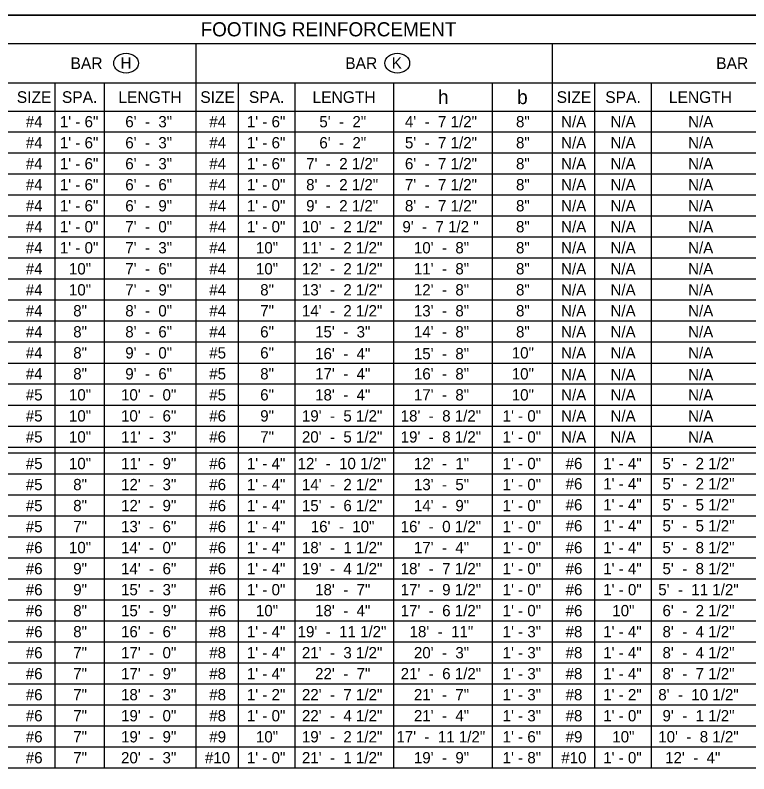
# Model space of a CAD drawing. Extents: x 99862 to 103151, y 100000 to 105076.
# Drawn here: x 100877 to 101917, y 104001 to 105076 of the extents above; entities that cross this region are included whole.
import ezdxf

# ---------------------------------------------------------------- set-up
doc = ezdxf.new("R2010")
doc.units = 0
for name, color, linetype in [('Level 1', 7, 'Continuous'), ('Level 20', 7, 'Continuous'), ('Level 4', 7, 'Continuous')]:
    doc.layers.add(name, color=color, linetype=linetype)

msp = doc.modelspace()

# ---------------------------------------------------------------- linework, layer by layer
at = {"layer": 'Level 1'}
msp.add_lwpolyline([(99862, 102999.5), (103151, 102999.5), (103151, 105075.5), (99862, 105075.5)], close=True, dxfattribs=at)
at = {"layer": 'Level 20'}
for centre in [(101034.5, 105007.5), (101418.9, 105007.5)]:
    msp.add_ellipse(centre, major_axis=(-17.5, 0), ratio=0.8, dxfattribs=at)
at = {"layer": 'Level 4'}
for p, q in [((100414, 105035.5), (102554, 105035.5)), ((101134, 104008.6), (101134, 105035.5)), ((101639, 104008.6), (101639, 105035.5)), ((100014, 104979.5), (102711, 104979.5)), ((100934, 104008.6), (100934, 104979.5)), ((101004, 104008.6), (101004, 104979.5)), ((101194, 104008.6), (101194, 104979.5)), ((101274, 104008.6), (101274, 104979.5)), ((101414, 104008.6), (101414, 104979.5)), ((101554, 104008.6), (101554, 104979.5)), ((101699, 104008.6), (101699, 104979.5)), ((101779, 104008.6), (101779, 104979.5)), ((99939, 104939.5), (103151, 104939.5)), ((103151, 104909.7), (99939, 104909.7)), ((103151, 104880), (99939, 104880)), ((103151, 104850.2), (99939, 104850.2)), ((103151, 104820.4), (99939, 104820.4)), ((103151, 104790.6), (99939, 104790.6)), ((103151, 104760.9), (99939, 104760.9)), ((103151, 104731.1), (99939, 104731.1)), ((103151, 104701.3), (99939, 104701.3)), ((103151, 104671.6), (99939, 104671.6)), ((103151, 104641.8), (99939, 104641.8)), ((103151, 104612), (99939, 104612)), ((103151, 104582.2), (99939, 104582.2)), ((103151, 104552.5), (99939, 104552.5)), ((103151, 104522.7), (99939, 104522.7)), ((103151, 104492.9), (99939, 104492.9)), ((103151, 104463.2), (99939, 104463.2)), ((103151, 104455.2), (99939, 104455.2)), ((103151, 104425.4), (99939, 104425.4)), ((103151, 104395.6), (99939, 104395.6)), ((103151, 104365.8), (99939, 104365.8)), ((103151, 104336.1), (99939, 104336.1)), ((103151, 104306.3), (99939, 104306.3)), ((103151, 104276.5), (99939, 104276.5)), ((103151, 104246.8), (99939, 104246.8)), ((103151, 104217), (99939, 104217)), ((103151, 104187.2), (99939, 104187.2)), ((103151, 104157.4), (99939, 104157.4)), ((103151, 104127.7), (99939, 104127.7)), ((103151, 104097.9), (99939, 104097.9)), ((103151, 104068.1), (99939, 104068.1)), ((103151, 104038.4), (99939, 104038.4))]:
    msp.add_line(p, q, dxfattribs=at)
for points in [[(99939, 105075.5), (103151, 105075.5)], [(103151, 104008.6), (99939, 104008.6), (99939, 105075.5)]]:
    msp.add_lwpolyline(points, dxfattribs=at)

# ---------------------------------------------------------------- texts
at = {"layer": 'Level 20'}
for s, height, p in [('FOOTING REINFORCEMENT', 20, (101140.2, 105045.5)), ('BAR', 16.5, (100955.8, 104999.2)), ('H', 16, (101026.7, 104999.7)), ('BAR', 16.5, (101345.1, 104999.2)), ('K', 16, (101411.1, 104999.7)), ('BAR', 16.5, (101870.8, 104999.2)), ('SIZE', 16.5, (100879.7, 104951.2)), ('SPA.', 16.5, (100943.6, 104951.2)), ('LENGTH', 16.5, (101023.7, 104951.2)), ('SIZE', 16.5, (101139.7, 104951.2)), ('SPA.', 16.5, (101208.6, 104951.2)), ('LENGTH', 16.5, (101298.7, 104951.2)), ('h', 20, (101476.6, 104949.5)), ('b', 20, (101588.8, 104949.5)), ('SIZE', 16.5, (101644.7, 104951.2)), ('SPA.', 16.5, (101713.6, 104951.2)), ('LENGTH', 16.5, (101803.7, 104951.2))]:
    msp.add_text(s, height=height, dxfattribs=at).set_placement(p)
for s, p in [('#4', (100892.4, 104916.6)), ('1\' - 6"', (100940.7, 104916.6)), ('6\'  -  3"', (101033.4, 104916.6)), ('#4', (101152.4, 104916.6)), ('1\' - 6"', (101205.7, 104916.6)), ('5\'  -  2"', (101308.4, 104916.6)), ('4\'  -  7 1/2"', (101429.7, 104916.6)), ('8"', (101587.1, 104916.6)), ('N/A', (101651, 104916.6)), ('N/A', (101721, 104916.6)), ('N/A', (101831, 104916.6)), ('5\'  -  7 1/2"', (101429.7, 104886.8)), ('N/A', (101651, 104886.8)), ('N/A', (101721, 104886.8)), ('N/A', (101831, 104886.8)), ('#4', (100892.4, 104886.8)), ('1\' - 6"', (100940.7, 104886.8)), ('6\'  -  3"', (101033.4, 104886.8)), ('#4', (101152.4, 104886.8)), ('1\' - 6"', (101205.7, 104886.8)), ('6\'  -  2"', (101308.4, 104886.8)), ('8"', (101587.1, 104886.8)), ('#4', (100892.4, 104857.1)), ('1\' - 6"', (100940.7, 104857.1)), ('6\'  -  3"', (101033.4, 104857.1)), ('#4', (101152.4, 104857.1)), ('1\' - 6"', (101205.7, 104857.1)), ('7\'  -  2 1/2"', (101289.7, 104857.1)), ('6\'  -  7 1/2"', (101429.7, 104857.1)), ('8"', (101587.1, 104857.1)), ('N/A', (101651, 104857.1)), ('N/A', (101721, 104857.1)), ('N/A', (101831, 104857.1)), ('#4', (100892.4, 104827.3)), ('1\' - 6"', (100940.7, 104827.3)), ('6\'  -  6"', (101033.4, 104827.3)), ('#4', (101152.4, 104827.3)), ('1\' - 0"', (101205.7, 104827.3)), ('8\'  -  2 1/2"', (101289.7, 104827.3)), ('7\'  -  7 1/2"', (101429.7, 104827.3)), ('8"', (101587.1, 104827.3)), ('N/A', (101651, 104827.3)), ('N/A', (101721, 104827.3)), ('N/A', (101831, 104827.3)), ('#4', (100892.4, 104797.5)), ('1\' - 6"', (100940.7, 104797.5)), ('6\'  -  9"', (101033.4, 104797.5)), ('#4', (101152.4, 104797.5)), ('1\' - 0"', (101205.7, 104797.5)), ('9\'  -  2 1/2"', (101289.7, 104797.5)), ('8\'  -  7 1/2"', (101429.7, 104797.5)), ('8"', (101587.1, 104797.5)), ('N/A', (101651, 104797.5)), ('N/A', (101721, 104797.5)), ('N/A', (101831, 104797.5)), ('#4', (100892.4, 104767.8)), ('1\' - 0"', (100940.7, 104767.8)), ('7\'  -  0"', (101033.4, 104767.8)), ('#4', (101152.4, 104767.8)), ('1\' - 0"', (101205.7, 104767.8)), ('10\'  -  2 1/2"', (101283.7, 104767.8)), ('9\'  -  7 1/2 "', (101426.1, 104767.8)), ('8"', (101587.1, 104767.8)), ('N/A', (101651, 104767.8)), ('N/A', (101721, 104767.8)), ('N/A', (101831, 104767.8)), ('#4', (100892.4, 104738)), ('1\' - 0"', (100940.7, 104738)), ('7\'  -  3"', (101033.4, 104738)), ('#4', (101152.4, 104738)), ('10"', (101218.6, 104738)), ('11\'  -  2 1/2"', (101283.7, 104738)), ('10\'  -  8"', (101442.4, 104738)), ('8"', (101587.1, 104738)), ('N/A', (101651, 104738)), ('N/A', (101721, 104738)), ('N/A', (101831, 104738)), ('#4', (100892.4, 104708.2)), ('10"', (100953.6, 104708.2)), ('7\'  -  6"', (101033.4, 104708.2)), ('#4', (101152.4, 104708.2)), ('10"', (101218.6, 104708.2)), ('12\'  -  2 1/2"', (101283.7, 104708.2)), ('11\'  -  8"', (101442.4, 104708.2)), ('8"', (101587.1, 104708.2)), ('N/A', (101651, 104708.2)), ('N/A', (101721, 104708.2)), ('N/A', (101831, 104708.2)), ('#4', (100892.4, 104678.4)), ('10"', (100953.6, 104678.4)), ('7\'  -  9"', (101033.4, 104678.4)), ('#4', (101152.4, 104678.4)), ('8"', (101224.6, 104678.4)), ('13\'  -  2 1/2"', (101283.7, 104678.4)), ('12\'  -  8"', (101442.4, 104678.4)), ('8"', (101587.1, 104678.4)), ('N/A', (101651, 104678.4)), ('N/A', (101721, 104678.4)), ('N/A', (101831, 104678.4)), ('#4', (100892.4, 104648.7)), ('8"', (100959.6, 104648.7)), ('8\'  -  0"', (101033.4, 104648.7)), ('#4', (101152.4, 104648.7)), ('7"', (101224.6, 104648.7)), ('14\'  -  2 1/2"', (101283.7, 104648.7)), ('13\'  -  8"', (101442.4, 104648.7)), ('8"', (101587.1, 104648.7)), ('N/A', (101651, 104648.7)), ('N/A', (101721, 104648.7)), ('N/A', (101831, 104648.7)), ('#4', (100892.4, 104618.9)), ('8"', (100959.6, 104618.9)), ('8\'  -  6"', (101033.4, 104618.9)), ('#4', (101152.4, 104618.9)), ('6"', (101224.6, 104618.9)), ('15\'  -  3"', (101302.4, 104618.9)), ('14\'  -  8"', (101442.4, 104618.9)), ('8"', (101587.1, 104618.9)), ('N/A', (101651, 104618.9)), ('N/A', (101721, 104618.9)), ('N/A', (101831, 104618.9)), ('#4', (100892.4, 104589.1)), ('8"', (100959.6, 104589.1)), ('9\'  -  0"', (101033.4, 104589.1)), ('#5', (101152.4, 104589.1)), ('6"', (101224.6, 104589.1)), ('16\'  -  4"', (101302.4, 104588)), ('15\'  -  8"', (101442.4, 104588)), ('10"', (101581.1, 104589.1)), ('N/A', (101651, 104589.1)), ('N/A', (101721, 104589.1)), ('N/A', (101831, 104589.1)), ('#4', (100892.4, 104559.4)), ('8"', (100959.6, 104559.4)), ('9\'  -  6"', (101033.4, 104559.4)), ('#5', (101152.4, 104559.4)), ('8"', (101224.6, 104559.4)), ('17\'  -  4"', (101302.4, 104559.4)), ('16\'  -  8"', (101442.4, 104559.4)), ('10"', (101581.1, 104559.4)), ('N/A', (101651, 104558.3)), ('N/A', (101721, 104558.3)), ('N/A', (101831, 104558.3)), ('#5', (100892.4, 104529.6)), ('10"', (100953.6, 104529.6)), ('10\'  -  0"', (101027.4, 104529.6)), ('#5', (101152.4, 104529.6)), ('6"', (101224.6, 104529.6)), ('18\'  -  4"', (101302.4, 104529.6)), ('17\'  -  8"', (101442.4, 104529.6)), ('10"', (101581.1, 104529.6)), ('N/A', (101651, 104529.6)), ('N/A', (101721, 104529.6)), ('N/A', (101831, 104529.6)), ('19\'  -  5 1/2"', (101283.7, 104499.8)), ('18\'  -  8 1/2"', (101423.7, 104499.8)), ('N/A', (101651, 104499.8)), ('N/A', (101721, 104499.8)), ('N/A', (101831, 104499.8)), ('#5', (100892.4, 104499.8)), ('10"', (100953.6, 104499.8)), ('10\'  -  6"', (101027.4, 104499.8)), ('#6', (101152.4, 104499.8)), ('9"', (101224.6, 104499.8)), ('1\' - 0"', (101568.2, 104499.8)), ('#5', (100892.4, 104470)), ('10"', (100953.6, 104470)), ('11\'  -  3"', (101027.4, 104470)), ('#6', (101152.4, 104470)), ('7"', (101224.6, 104470)), ('20\'  -  5 1/2"', (101283.7, 104470)), ('19\'  -  8 1/2"', (101423.7, 104470)), ('1\' - 0"', (101568.2, 104470)), ('N/A', (101651, 104470)), ('N/A', (101721, 104470)), ('N/A', (101831, 104470)), ('#5', (100892.4, 104432.3)), ('10"', (100953.6, 104432.3)), ('11\'  -  9"', (101027.4, 104432.3)), ('#6', (101152.4, 104432.3)), ('1\' - 4"', (101205.7, 104432.3)), ('12\'  -  10 1/2"', (101277.6, 104432.3)), ('12\'  -  1"', (101442.4, 104432.3)), ('1\' - 0"', (101568.2, 104432.3)), ('#6', (101657.4, 104432.3)), ('1\' - 4"', (101710.7, 104432.3)), ('5\'  -  2 1/2"', (101794.7, 104432.3)), ('#6', (101657.4, 104403.6)), ('1\' - 4"', (101710.7, 104403.6)), ('5\'  -  2 1/2"', (101794.7, 104403.6)), ('#5', (100892.4, 104402.5)), ('8"', (100959.6, 104402.5)), ('12\'  -  3"', (101027.4, 104402.5)), ('#6', (101152.4, 104402.5)), ('1\' - 4"', (101205.7, 104402.5)), ('14\'  -  2 1/2"', (101283.7, 104402.5)), ('13\'  -  5"', (101442.4, 104402.5)), ('1\' - 0"', (101568.2, 104402.5)), ('#5', (100892.4, 104372.7)), ('8"', (100959.6, 104372.7)), ('12\'  -  9"', (101027.4, 104372.7)), ('#6', (101152.4, 104372.7)), ('1\' - 4"', (101205.7, 104372.7)), ('15\'  -  6 1/2"', (101283.7, 104372.7)), ('14\'  -  9"', (101442.4, 104372.7)), ('1\' - 0"', (101568.2, 104372.7)), ('#6', (101657.4, 104373.8)), ('1\' - 4"', (101710.7, 104373.8)), ('5\'  -  5 1/2"', (101794.7, 104373.8)), ('#5', (100892.4, 104343)), ('7"', (100959.6, 104343)), ('13\'  -  6"', (101027.4, 104343)), ('#6', (101152.4, 104343)), ('1\' - 4"', (101205.7, 104343)), ('16\'  -  10"', (101296.3, 104343)), ('16\'  -  0 1/2"', (101423.7, 104343)), ('1\' - 0"', (101568.2, 104343)), ('#6', (101657.4, 104344.1)), ('1\' - 4"', (101710.7, 104344.1)), ('5\'  -  5 1/2"', (101794.7, 104344.1)), ('#6', (100892.4, 104313.2)), ('10"', (100953.6, 104313.2)), ('14\'  -  0"', (101027.4, 104313.2)), ('#6', (101152.4, 104313.2)), ('1\' - 4"', (101205.7, 104313.2)), ('18\'  -  1 1/2"', (101283.7, 104313.2)), ('17\'  -  4"', (101442.4, 104313.2)), ('1\' - 0"', (101568.2, 104313.2)), ('#6', (101657.4, 104313.2)), ('1\' - 4"', (101710.7, 104313.2)), ('5\'  -  8 1/2"', (101794.7, 104313.2)), ('#6', (100892.4, 104283.4)), ('9"', (100959.6, 104283.4)), ('14\'  -  6"', (101027.4, 104283.4)), ('#6', (101152.4, 104283.4)), ('1\' - 4"', (101205.7, 104283.4)), ('19\'  -  4 1/2"', (101283.7, 104283.4)), ('18\'  -  7 1/2"', (101423.7, 104283.4)), ('1\' - 0"', (101568.2, 104283.4)), ('#6', (101657.4, 104283.4)), ('1\' - 4"', (101710.7, 104283.4)), ('5\'  -  8 1/2"', (101794.7, 104283.4)), ('#6', (100892.4, 104253.6)), ('9"', (100959.6, 104253.6)), ('15\'  -  3"', (101027.4, 104253.6)), ('#6', (101152.4, 104253.6)), ('1\' - 0"', (101205.7, 104253.6)), ('18\'  -  7"', (101302.4, 104253.6)), ('17\'  -  9 1/2"', (101423.7, 104253.6)), ('1\' - 0"', (101568.2, 104253.6)), ('#6', (101657.4, 104253.6)), ('1\' - 0"', (101710.7, 104253.6)), ('5\'  -  11 1/2"', (101788.7, 104253.6)), ('#6', (100892.4, 104223.9)), ('8"', (100959.6, 104223.9)), ('15\'  -  9"', (101027.4, 104223.9)), ('#6', (101152.4, 104223.9)), ('10"', (101218.6, 104223.9)), ('18\'  -  4"', (101302.4, 104223.9)), ('17\'  -  6 1/2"', (101423.7, 104223.9)), ('1\' - 0"', (101568.2, 104223.9)), ('#6', (101657.4, 104223.9)), ('10"', (101723.6, 104223.9)), ('6\'  -  2 1/2"', (101794.7, 104223.9)), ('#6', (100892.4, 104194.1)), ('8"', (100959.6, 104194.1)), ('16\'  -  6"', (101027.4, 104194.1)), ('#8', (101152.4, 104194.1)), ('1\' - 4"', (101205.7, 104194.1)), ('19\'  -  11 1/2"', (101277.6, 104194.1)), ('18\'  -  11"', (101436.3, 104194.1)), ('1\' - 3"', (101568.2, 104194.1)), ('#8', (101657.4, 104194.1)), ('1\' - 4"', (101710.7, 104194.1)), ('8\'  -  4 1/2"', (101794.7, 104194.1)), ('#6', (100892.4, 104164.3)), ('7"', (100959.6, 104164.3)), ('17\'  -  0"', (101027.4, 104164.3)), ('#8', (101152.4, 104164.3)), ('1\' - 4"', (101205.7, 104164.3)), ('21\'  -  3 1/2"', (101283.7, 104164.3)), ('20\'  -  3"', (101442.4, 104164.3)), ('1\' - 3"', (101568.2, 104164.3)), ('#8', (101657.4, 104164.3)), ('1\' - 4"', (101710.7, 104164.3)), ('8\'  -  4 1/2"', (101794.7, 104164.3)), ('21\'  -  6 1/2"', (101423.7, 104134.6)), ('8\'  -  7 1/2"', (101794.7, 104134.6)), ('#6', (100892.4, 104134.6)), ('7"', (100959.6, 104134.6)), ('17\'  -  9"', (101027.4, 104134.6)), ('#8', (101152.4, 104134.6)), ('1\' - 4"', (101205.7, 104134.6)), ('22\'  -  7"', (101302.4, 104134.6)), ('1\' - 3"', (101568.2, 104134.6)), ('#8', (101657.4, 104134.6)), ('1\' - 4"', (101710.7, 104134.6)), ('#6', (100892.4, 104104.8)), ('7"', (100959.6, 104104.8)), ('18\'  -  3"', (101027.4, 104104.8)), ('#8', (101152.4, 104104.8)), ('1\' - 2"', (101205.7, 104104.8)), ('22\'  -  7 1/2"', (101283.7, 104104.8)), ('21\'  -  7"', (101442.4, 104104.8)), ('1\' - 3"', (101568.2, 104104.8)), ('#8', (101657.4, 104104.8)), ('1\' - 2"', (101710.7, 104104.8)), ('8\'  -  10 1/2"', (101788.7, 104104.8)), ('#6', (100892.4, 104075)), ('7"', (100959.6, 104075)), ('19\'  -  0"', (101027.4, 104075)), ('#8', (101152.4, 104075)), ('1\' - 0"', (101205.7, 104075)), ('22\'  -  4 1/2"', (101283.7, 104075)), ('21\'  -  4"', (101442.4, 104075)), ('1\' - 3"', (101568.2, 104075)), ('#8', (101657.4, 104075)), ('1\' - 0"', (101710.7, 104075)), ('9\'  -  1 1/2"', (101794.7, 104075)), ('#6', (100892.4, 104045.2)), ('7"', (100959.6, 104045.2)), ('19\'  -  9"', (101027.4, 104045.2)), ('#9', (101152.4, 104045.2)), ('10"', (101218.6, 104045.2)), ('19\'  -  2 1/2"', (101283.7, 104045.2)), ('17\'  -  11 1/2"', (101417.6, 104045.2)), ('1\' - 6"', (101568.2, 104045.2)), ('#9', (101657.4, 104045.2)), ('10"', (101723.6, 104045.2)), ('10\'  -  8 1/2"', (101788.7, 104045.2)), ('#6', (100892.4, 104015.5)), ('7"', (100959.6, 104015.5)), ('20\'  -  3"', (101027.4, 104015.5)), ('#10', (101146.3, 104015.5)), ('1\' - 0"', (101205.7, 104015.5)), ('21\'  -  1 1/2"', (101283.7, 104015.5)), ('19\'  -  9"', (101442.4, 104015.5)), ('1\' - 8"', (101568.2, 104015.5)), ('#10', (101651.3, 104015.5)), ('1\' - 0"', (101710.7, 104015.5)), ('12\'  -  4"', (101798.4, 104015.5))]:
    msp.add_text(s, height=16, rotation=360, dxfattribs=at).set_placement(p)

doc.saveas('drawing.dxf')
